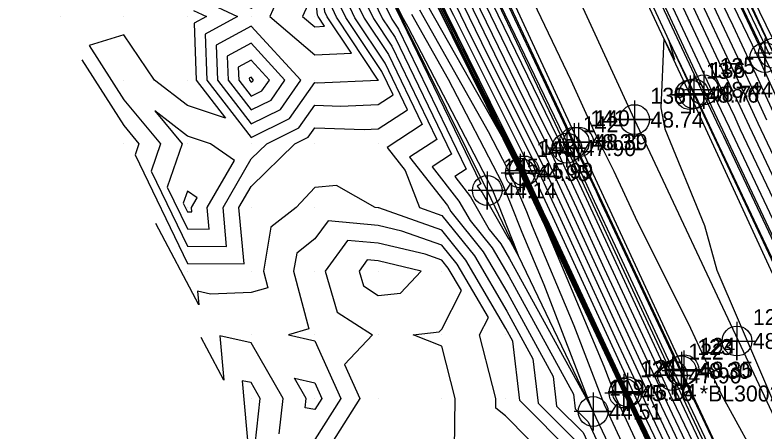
# Model space of a CAD drawing. Extents: x 2090860 to 2091277, y 159470 to 160080.
# Drawn here: x 2091052.9 to 2091170.8, y 159524.7 to 159590.2 of the extents above; entities that cross this region are included whole.
import ezdxf

# ---------------------------------------------------------------- set-up
doc = ezdxf.new("R2010")
doc.units = 0
for name, color, linetype in [('DTM Contours Major', 7, 'Continuous'), ('DTM Contours Minor', 7, 'Continuous'), ('Exist DTM Breakline', 7, 'Continuous'), ('Exist DTM Breakline Cogo Elevation', 7, 'Continuous'), ('Exist DTM Breakline Cogo Number', 7, 'Continuous'), ('Exist DTM Breakline Cogo Point CELL', 7, 'Continuous'), ('Exist DTM Crownline', 7, 'Continuous'), ('Exist DTM Crownline Cogo Elevation', 7, 'Continuous'), ('Exist DTM Crownline Cogo Number', 7, 'Continuous'), ('Exist DTM Crownline Cogo Point CELL', 7, 'Continuous'), ('Exist DTM QL2 LIDAR Elevation Point', 7, 'Continuous'), ('Exist Roads EOP', 7, 'Continuous'), ('Exist Roads EOP Cogo Elevation', 7, 'Continuous'), ('Exist Roads EOP Cogo Number', 7, 'Continuous'), ('Exist Roads EOP Cogo Point CELL', 7, 'Continuous'), ('Exist Roads EOT', 7, 'Continuous'), ('Exist Roads EOT Cogo Comment', 7, 'Continuous'), ('Exist Roads EOT Cogo Elevation', 7, 'Continuous'), ('Exist Roads EOT Cogo Number', 7, 'Continuous'), ('Exist Roads EOT Cogo Point CELL', 7, 'Continuous')]:
    doc.layers.add(name, color=color, linetype=linetype)

msp = doc.modelspace()

# ---------------------------------------------------------------- linework, layer by layer
at = {"layer": 'DTM Contours Major'}
for points in [[(2091110.01, 159579.99), (2091110, 159580), (2091103.43, 159589.88), (2091102.78, 159591.23), (2091101.95, 159599.1), (2091099.75, 159604.35), (2091092.87, 159614.02), (2091090, 159617.82), (2091083.3, 159616.7), (2091082.04, 159610), (2091081.38, 159608.62), (2091081.89, 159600), (2091082.49, 159592.49), (2091087.89, 159590), (2091082.79, 159587.21), (2091083.05, 159580), (2091090, 159570.96), (2091096.05, 159573.95), (2091100, 159579.61), (2091100.41, 159579.59), (2091110, 159579.99), (2091110.01, 159579.99)], [(2091171.96, 159584.5), (2091159.16, 159611.27)], [(2091172.41, 159574.21), (2091169.37, 159580.83), (2091168.62, 159582.42), (2091165.76, 159588.52), (2091155.65, 159609.47)], [(2091176.73, 159551.58), (2091166.95, 159572.18), (2091166.02, 159574.22), (2091163.43, 159579.67), (2091153.6, 159600.61)], [(2091123.21, 159594.52), (2091129.91, 159580.68), (2091136.47, 159567.62), (2091138.12, 159564.05), (2091140.2, 159559.58), (2091146.27, 159546.39), (2091152.79, 159532.35), (2091156.16, 159525.23), (2091159.5, 159518.23), (2091166.04, 159504.37), (2091172.36, 159491.13)], [(2091128.34, 159593.56), (2091139.93, 159569.54), (2091140.97, 159567.34), (2091143.92, 159560.98), (2091147.21, 159553.98), (2091156.59, 159533.79), (2091161.27, 159523.96), (2091163.21, 159519.86), (2091171.58, 159502.29)], [(2091107.49, 159593.3), (2091109.23, 159589.68), (2091112.12, 159585.33), (2091119.2, 159570.67), (2091114.92, 159567.89), (2091120.85, 159560.32), (2091121.4, 159559.35), (2091126.5, 159553), (2091130.34, 159546.45), (2091137.49, 159533.43), (2091138.02, 159528.79), (2091142.19, 159524.62), (2091146.07, 159516.26), (2091147.17, 159512.31), (2091150.06, 159501.29), (2091151.2, 159498.79), (2091159.61, 159487.39), (2091158.87, 159484.16)], [(2091119.62, 159592.62), (2091130.86, 159569.9), (2091132.95, 159565.75), (2091135.92, 159559.3), (2091136.42, 159558.22), (2091136.43, 159558.2), (2091136.46, 159558.15), (2091149.11, 159531.02), (2091149.46, 159530.28), (2091156.03, 159516.65), (2091157.29, 159514), (2091169.04, 159489.62), (2091168.66, 159489.37)], [(2091165.38, 159487.43), (2091166.95, 159488.49), (2091162.97, 159496.65), (2091154.19, 159515.65), (2091152.26, 159519.58), (2091147.4, 159530.11), (2091145.52, 159535.03), (2091136.24, 159557.07), (2091135.82, 159557.96), (2091132.52, 159565.03), (2091132.34, 159565.41), (2091129.86, 159570.34), (2091117.8, 159591.64)], [(2091090.23, 159579.77), (2091090.4, 159580), (2091090, 159580.43), (2091089.72, 159580.28), (2091089.73, 159580), (2091090, 159579.65), (2091090.23, 159579.77)], [(2091083.12, 159560), (2091087.39, 159567.39), (2091083.6, 159570), (2091080, 159571.2), (2091074.86, 159575.14), (2091079.15, 159570), (2091076.83, 159563.17), (2091080, 159556.61), (2091083.43, 159556.57), (2091083.12, 159560)], [(2091121.95, 159521.95), (2091122.09, 159530), (2091120, 159538.21), (2091115.49, 159540), (2091119.57, 159540.43), (2091120, 159540.89), (2091123.06, 159546.94), (2091121, 159550.46), (2091120, 159551.7), (2091117.36, 159552.64), (2091110, 159554.37), (2091105.18, 159554.82), (2091101.62, 159550), (2091103.54, 159543.54), (2091109.08, 159540), (2091104.66, 159535.34), (2091107.07, 159530), (2091102.04, 159522.04)], [(2091091.07, 159517.86), (2091090.65, 159519.35), (2091092.62, 159520), (2091090.36, 159520.36), (2091091.43, 159530), (2091090, 159532.48), (2091088.61, 159532.78), (2091089.65, 159521.06), (2091089.36, 159521.61)]]:
    msp.add_lwpolyline(points, dxfattribs=at)
at = {"layer": 'DTM Contours Minor'}
for points in [[(2091101.98, 159589.93), (2091101.61, 159590.71), (2091100.66, 159599.7), (2091099.92, 159601.47), (2091091.93, 159612.69), (2091090, 159615.24), (2091085.51, 159614.49), (2091084.66, 159610), (2091083.16, 159606.84), (2091083.56, 159600), (2091084.04, 159594.04), (2091090, 159591.29), (2091095.28, 159595.28), (2091092.94, 159590), (2091100, 159583.94), (2091105.79, 159584.21), (2091101.98, 159589.93)], [(2091173.78, 159574.72), (2091170.21, 159582.49), (2091169.92, 159583.11), (2091168.8, 159585.5), (2091156.91, 159610.13)], [(2091172.91, 159584.62), (2091161.2, 159608.69)], [(2091170.96, 159583.65), (2091159.14, 159608.41)], [(2091177.06, 159547.51), (2091165.59, 159571.67), (2091165.18, 159572.56), (2091162.13, 159578.99), (2091150.56, 159603.64)], [(2091131.42, 159598.52), (2091140.27, 159579.96), (2091144.16, 159571.35), (2091147, 159565.67), (2091150.37, 159558.45), (2091159.04, 159541.04), (2091163.85, 159530.74), (2091168.57, 159522.2), (2091174.47, 159509.57)], [(2091175.38, 159547.74), (2091164.28, 159571.14), (2091163.68, 159572.41), (2091160.86, 159578.35), (2091151.1, 159599.18)], [(2091127.83, 159563.02), (2091114.71, 159588.31), (2091113.97, 159589.62), (2091111.29, 159594.84), (2091111.22, 159594.96), (2091109.89, 159597.62), (2091111, 159594.95), (2091111.01, 159594.86), (2091113.57, 159589.53), (2091113.71, 159589.32), (2091126.1, 159563.68), (2091125.55, 159563.32), (2091126.31, 159562.35), (2091130.43, 159555.15), (2091130.63, 159554.91), (2091130.78, 159554.65), (2091132.15, 159552.14), (2091131.36, 159554.21), (2091130.99, 159555.1), (2091128.25, 159562.04), (2091127.83, 159563.02)], [(2091127.82, 159597.21), (2091138.56, 159574.44), (2091140.64, 159570.11), (2091144.22, 159562.5), (2091144.73, 159561.4), (2091156.04, 159537.32), (2091157.47, 159534.24), (2091158.19, 159532.74), (2091164.14, 159520.13), (2091165.09, 159518.14), (2091176.96, 159492.99)], [(2091176.41, 159555.65), (2091168.32, 159572.69), (2091166.86, 159575.87), (2091164.73, 159580.36), (2091156.64, 159597.59)], [(2091126.02, 159596), (2091138.04, 159571.18), (2091139.12, 159569.03), (2091139.39, 159568.44), (2091143.03, 159560.61), (2091144.03, 159558.44), (2091155.66, 159533.4), (2091156.21, 159532.23), (2091162.28, 159519.5), (2091163.24, 159517.46), (2091175.19, 159492.42)], [(2091171.53, 159583.93), (2091165.55, 159596.46)], [(2091124.14, 159595.01), (2091132.62, 159577.51), (2091137.36, 159568.09), (2091138.54, 159565.51), (2091141.14, 159559.92), (2091145.52, 159550.4), (2091153.75, 159532.7), (2091156.17, 159527.57), (2091160.42, 159518.66), (2091165.11, 159508.73), (2091173.3, 159491.56)], [(2091125.08, 159595.51), (2091135.33, 159574.35), (2091138.24, 159568.56), (2091138.97, 159566.98), (2091142.08, 159560.26), (2091144.77, 159554.42), (2091154.7, 159533.05), (2091156.19, 159529.9), (2091161.35, 159519.08), (2091164.18, 159513.1), (2091174.25, 159491.99)], [(2091176.08, 159559.72), (2091169.68, 159573.2), (2091167.7, 159577.53), (2091166.02, 159581.05), (2091159.68, 159594.57)], [(2091100.54, 159589.98), (2091100.43, 159590.19), (2091100, 159594.3), (2091098.09, 159590), (2091100, 159588.36), (2091101.56, 159588.44), (2091100.54, 159589.98)], [(2091108.66, 159593.82), (2091110.67, 159589.63), (2091112.65, 159586.66), (2091121.5, 159568.34), (2091118.46, 159566.36), (2091122.67, 159560.99), (2091124.41, 159557.95), (2091127.88, 159553.64), (2091130.49, 159549.18), (2091140.66, 159530.65), (2091140.93, 159528.36), (2091142.99, 159526.29), (2091148.27, 159514.9), (2091148.85, 159512.85), (2091150.34, 159507.13), (2091156.63, 159493.3), (2091161.33, 159486.92), (2091160.92, 159485.12)], [(2091109.84, 159594.34), (2091112.12, 159589.58), (2091113.18, 159587.99), (2091123.8, 159566.01), (2091122, 159564.84), (2091124.49, 159561.67), (2091127.42, 159556.55), (2091129.25, 159554.27), (2091130.63, 159551.92), (2091143.49, 159528.5), (2091136.08, 159547.82), (2091132.61, 159556.06), (2091130.79, 159560.67), (2091129.44, 159563.87)], [(2091121.34, 159593.53), (2091124.5, 159587.01), (2091134.71, 159566.68), (2091137.27, 159561.12), (2091138.31, 159558.89), (2091147.77, 159538.35), (2091150.88, 159531.66), (2091156.12, 159520.56), (2091157.64, 159517.38), (2091167.91, 159495.64), (2091170.47, 159490.27), (2091170.45, 159490.22)], [(2091122.27, 159594.02), (2091127.2, 159583.84), (2091135.59, 159567.15), (2091137.7, 159562.59), (2091139.25, 159559.23), (2091147.02, 159542.37), (2091151.83, 159532.01), (2091156.14, 159522.9), (2091158.57, 159517.81), (2091166.98, 159500), (2091171.42, 159490.7)], [(2091063.4, 159583.2), (2091070, 159572.84), (2091072.37, 159570), (2091071.77, 159568.23), (2091080, 159551.21), (2091088.89, 159551.11), (2091088.09, 159560), (2091090, 159563.3), (2091096.86, 159570), (2091098.96, 159571.04), (2091100, 159572.52), (2091107.76, 159572.24), (2091110, 159572.33), (2091114.6, 159575.33), (2091111.06, 159582.67), (2091106.33, 159589.78), (2091105.13, 159592.26)], [(2091106.31, 159592.78), (2091107.78, 159589.73), (2091111.59, 159584), (2091116.9, 159573), (2091111.38, 159569.41), (2091114.22, 159565.78), (2091116.48, 159560), (2091120, 159558.75), (2091125.12, 159552.37), (2091130.2, 159543.71), (2091134.31, 159536.22), (2091135.12, 159529.23), (2091141.39, 159522.94), (2091143.86, 159517.62), (2091145.5, 159511.77), (2091148.09, 159501.91), (2091148.63, 159500), (2091150, 159498.55), (2091157.89, 159487.86), (2091156.82, 159483.2)], [(2091119.2, 159592.39), (2091123.93, 159582.84), (2091132.63, 159565.57), (2091134.47, 159561.63), (2091136.12, 159558.08), (2091143.73, 159541.81), (2091148.81, 159530.9), (2091153.14, 159521.79), (2091155.67, 159516.52), (2091164.42, 159498.08), (2091168.58, 159489.45), (2091167.02, 159488.4)], [(2091119.41, 159592.5), (2091128.51, 159574.11), (2091132.78, 159565.65), (2091135.45, 159559.92), (2091136.28, 159558.14), (2091140.09, 159549.98), (2091148.96, 159530.96), (2091151.3, 159526.03), (2091155.85, 159516.59), (2091160.85, 159506.04), (2091168.81, 159489.54), (2091167.84, 159488.89)], [(2091120.4, 159593.03), (2091121.79, 159590.17), (2091133.83, 159566.21), (2091136.85, 159559.66), (2091137.37, 159558.55), (2091148.52, 159534.34), (2091149.92, 159531.31), (2091156.11, 159518.23), (2091156.71, 159516.96), (2091168.84, 159491.27), (2091169.53, 159489.84), (2091169.52, 159489.83)], [(2091112.31, 159577.66), (2091110.53, 159581.34), (2091104.88, 159589.83), (2091103.96, 159591.75)], [(2091164.56, 159486.95), (2091165.44, 159487.54), (2091157.04, 159504.73), (2091152.48, 159514.58), (2091147.96, 159523.81), (2091145.56, 159529.01), (2091140.8, 159541.42), (2091134.23, 159557.02), (2091133.33, 159559.3), (2091131.04, 159564.72), (2091127.32, 159571.89), (2091116.53, 159590.97)], [(2091166.2, 159487.92), (2091168.35, 159489.36), (2091167.98, 159490.11), (2091155.5, 159516.46), (2091154.97, 159517.54), (2091148.66, 159530.85), (2091147.36, 159533.64), (2091135.97, 159558.02), (2091133.49, 159563.33), (2091132.49, 159565.49), (2091119.34, 159591.57)], [(2091171.05, 159573.7), (2091168.54, 159579.18), (2091167.32, 159581.74), (2091162.72, 159591.55)], [(2091080.94, 159590.94), (2091082.99, 159590), (2091081.06, 159588.94), (2091081.38, 159580), (2091085.98, 159574.02), (2091080, 159576.01), (2091074.8, 159580), (2091070, 159587.09), (2091064.56, 159585.44), (2091070, 159576.9), (2091075.76, 159570), (2091074.3, 159565.7), (2091080, 159553.91), (2091086.16, 159553.84), (2091085.6, 159560), (2091090, 159567.61), (2091092.45, 159570), (2091097.51, 159572.49), (2091100, 159576.07), (2091104.08, 159575.92), (2091110, 159576.16), (2091112.31, 159577.66)], [(2091129.44, 159563.87), (2091121.02, 159580.1), (2091115.25, 159590.29)], [(2091094.6, 159575.4), (2091097.8, 159580), (2091090, 159588.47), (2091084.52, 159585.48), (2091084.72, 159580), (2091090, 159573.13), (2091094.6, 159575.4)], [(2091175.98, 159543.39), (2091164.06, 159568.64), (2091163.17, 159570.51), (2091159.88, 159577.48), (2091159.69, 159577.88), (2091159.03, 159579.28), (2091155.63, 159586.39), (2091156.55, 159583.25), (2091154.87, 159586.53), (2091154.4, 159575.64), (2091155.02, 159572.33), (2091161.24, 159557.18), (2091163.19, 159550.12), (2091173.59, 159526.02)], [(2091093.14, 159576.86), (2091095.33, 159580), (2091090, 159585.79), (2091086.26, 159583.74), (2091086.39, 159580), (2091090, 159575.31), (2091093.14, 159576.86)], [(2091091.69, 159578.31), (2091092.87, 159580), (2091090, 159583.11), (2091087.99, 159582.01), (2091088.06, 159580), (2091090, 159577.48), (2091091.69, 159578.31)], [(2091140.6, 159521.26), (2091132.22, 159529.67), (2091131.14, 159539), (2091130.05, 159540.98), (2091123.75, 159551.73), (2091120, 159556.4), (2091110.06, 159559.94), (2091110, 159559.95), (2091109.48, 159560), (2091103.44, 159563.44), (2091100, 159563.1), (2091097.06, 159560), (2091093.12, 159556.88), (2091091.93, 159550), (2091092.62, 159547.38), (2091090, 159546.63), (2091083.61, 159546.39), (2091081.58, 159546.84), (2091081.77, 159544.68), (2091075.01, 159557.47)], [(2091080.63, 159560), (2091081.5, 159561.5), (2091080, 159562.54), (2091079.35, 159560.65), (2091080, 159559.31), (2091080.7, 159559.3), (2091080.63, 159560)], [(2091137.15, 159520), (2091130, 159527.24), (2091128.46, 159528.46), (2091128.48, 159530), (2091127.97, 159532.03), (2091125.91, 159540), (2091127.29, 159542.71), (2091122.37, 159551.1), (2091120, 159554.05), (2091113.71, 159556.29), (2091110, 159557.16), (2091102.1, 159557.9), (2091100, 159555.06), (2091097.17, 159552.83), (2091096.69, 159550), (2091099.08, 159540.92), (2091095.88, 159540), (2091100, 159539.06), (2091104.09, 159530), (2091100, 159523.53)], [(2091110, 159551.58), (2091108.26, 159551.74), (2091106.97, 159550), (2091107.66, 159547.66), (2091110, 159546.17), (2091113.46, 159546.54), (2091116.73, 159550), (2091110, 159551.58)], [(2091094.43, 159524.43), (2091095.04, 159530), (2091090, 159538.73), (2091085.09, 159539.81), (2091085.71, 159532.87), (2091082.18, 159539.54)], [(2091096.82, 159533.18), (2091100, 159532.46), (2091101.11, 159530), (2091100, 159528.24), (2091098.49, 159528.49), (2091098.65, 159530), (2091096.82, 159533.18)]]:
    msp.add_lwpolyline(points, dxfattribs=at)
at = {"layer": 'Exist DTM Breakline'}
for points in [[(2091196.63, 159502.87), (2091177.33, 159544.14), (2091161.14, 159578.46), (2091145.39, 159612.39), (2091128.08, 159650.69), (2091112.84, 159682.38), (2091098.52, 159713.45), (2091088.42, 159738.26), (2091087.49, 159747.73)], [(2091206.49, 159507.9), (2091187.96, 159548.13), (2091170.75, 159583.55), (2091154.78, 159617.35), (2091136.61, 159654.77), (2091121.99, 159686.47), (2091108.44, 159717.46), (2091100.12, 159738.88)], [(2091168.33, 159489.35), (2091148.61, 159530.83), (2091132.31, 159565.39), (2091116.34, 159597.57), (2091098.7, 159637.59), (2091084.7, 159667.25), (2091067.16, 159699.24), (2091053.41, 159724.44), (2091052.89, 159730.3), (2091057.39, 159734.95)], [(2091169.18, 159489.68), (2091149.14, 159531.03), (2091132.91, 159565.73), (2091117.09, 159597.89), (2091099.25, 159637.73), (2091085.44, 159667.51), (2091069.3, 159700.06), (2091060.28, 159722.82), (2091058.46, 159734.2), (2091059.36, 159735), (2091060.62, 159735.81)], [(2091175.56, 159492.59), (2091156.22, 159533.6), (2091139.64, 159569.31), (2091124.33, 159601.66), (2091105.94, 159640.92), (2091091.73, 159670.47), (2091076.45, 159703.52), (2091059.36, 159735)], [(2091163.51, 159486.33), (2091143.76, 159527.93), (2091127.12, 159562.65), (2091111.11, 159594.9), (2091093.03, 159634.87), (2091078.89, 159664.39)], [(2091208.29, 159508.47), (2091189.15, 159548.51), (2091172.11, 159584.22), (2091156.47, 159618.15), (2091137.83, 159655.46)]]:
    msp.add_lwpolyline(points, dxfattribs=at)
at = {"layer": 'Exist DTM Breakline Cogo Point CELL'}
for points in [[(2091170.75, 159586.55), (2091170.75, 159580.55), (2091170.75, 159583.55), (2091173.75, 159583.55), (2091167.75, 159583.55)], [(2091172.11, 159587.22), (2091172.11, 159581.22), (2091172.11, 159584.22), (2091175.11, 159584.22), (2091169.11, 159584.22)], [(2091161.14, 159581.46), (2091161.14, 159575.46), (2091161.14, 159578.46), (2091164.14, 159578.46), (2091158.14, 159578.46)], [(2091139.64, 159572.31), (2091139.64, 159566.31), (2091139.64, 159569.31), (2091142.64, 159569.31), (2091136.64, 159569.31)], [(2091132.91, 159568.73), (2091132.91, 159562.73), (2091132.91, 159565.73), (2091135.91, 159565.73), (2091129.91, 159565.73)], [(2091132.31, 159568.39), (2091132.31, 159562.39), (2091132.31, 159565.39), (2091135.31, 159565.39), (2091129.31, 159565.39)], [(2091127.12, 159565.65), (2091127.12, 159559.65), (2091127.12, 159562.65), (2091130.12, 159562.65), (2091124.12, 159562.65)], [(2091156.22, 159536.6), (2091156.22, 159530.6), (2091156.22, 159533.6), (2091159.22, 159533.6), (2091153.22, 159533.6)], [(2091148.61, 159533.83), (2091148.61, 159527.83), (2091148.61, 159530.83), (2091151.61, 159530.83), (2091145.61, 159530.83)], [(2091149.14, 159534.03), (2091149.14, 159528.03), (2091149.14, 159531.03), (2091152.14, 159531.03), (2091146.14, 159531.03)], [(2091143.76, 159530.93), (2091143.76, 159524.93), (2091143.76, 159527.93), (2091146.76, 159527.93), (2091140.76, 159527.93)]]:
    msp.add_lwpolyline(points, dxfattribs=at)
for centre in [(2091172.11, 159584.22), (2091170.75, 159583.55), (2091161.14, 159578.46), (2091139.64, 159569.31), (2091132.31, 159565.39), (2091132.91, 159565.73), (2091127.12, 159562.65), (2091156.22, 159533.6), (2091149.14, 159531.03), (2091148.61, 159530.83), (2091143.76, 159527.93)]:
    msp.add_circle(centre, 2.34, dxfattribs=at)
at = {"layer": 'Exist DTM Crownline'}
msp.add_lwpolyline([(2091186.23, 159497.37), (2091150.27, 159573.79), (2091135.08, 159606.79), (2091117.27, 159645.44), (2091102.61, 159676.95), (2091088.1, 159708.38), (2091072.92, 159741.27)], dxfattribs=at)
at = {"layer": 'Exist DTM Crownline Cogo Point CELL'}
msp.add_lwpolyline([(2091150.27, 159576.79), (2091150.27, 159570.79), (2091150.27, 159573.79), (2091153.27, 159573.79), (2091147.27, 159573.79)], dxfattribs=at)
msp.add_circle((2091150.27, 159573.79), 2.34, dxfattribs=at)
at = {"layer": 'Exist DTM QL2 LIDAR Elevation Point'}
for p, q in [((2091060, 159590), (2091060, 159590)), ((2091070, 159590), (2091070, 159590)), ((2091080, 159590), (2091080, 159590)), ((2091090, 159590), (2091090, 159590)), ((2091100, 159590), (2091100, 159590)), ((2091070, 159580), (2091070, 159580)), ((2091080, 159580), (2091080, 159580)), ((2091090, 159580), (2091090, 159580)), ((2091100, 159580), (2091100, 159580)), ((2091110, 159580), (2091110, 159580)), ((2091070, 159570), (2091070, 159570)), ((2091080, 159570), (2091080, 159570)), ((2091090, 159570), (2091090, 159570)), ((2091100, 159570), (2091100, 159570)), ((2091110, 159570), (2091110, 159570)), ((2091080, 159560), (2091080, 159560)), ((2091090, 159560), (2091090, 159560)), ((2091100, 159560), (2091100, 159560)), ((2091110, 159560), (2091110, 159560)), ((2091120, 159560), (2091120, 159560)), ((2091080, 159550), (2091080, 159550)), ((2091090, 159550), (2091090, 159550)), ((2091100, 159550), (2091100, 159550)), ((2091110, 159550), (2091110, 159550)), ((2091120, 159550), (2091120, 159550)), ((2091090, 159540), (2091090, 159540)), ((2091100, 159540), (2091100, 159540)), ((2091110, 159540), (2091110, 159540)), ((2091120, 159540), (2091120, 159540)), ((2091130, 159540), (2091130, 159540)), ((2091090, 159530), (2091090, 159530)), ((2091100, 159530), (2091100, 159530)), ((2091110, 159530), (2091110, 159530)), ((2091120, 159530), (2091120, 159530)), ((2091130, 159530), (2091130, 159530))]:
    msp.add_line(p, q, dxfattribs=at)
at = {"layer": 'Exist Roads EOP'}
for points in [[(2091195.02, 159502.3), (2091175.82, 159543.3), (2091159.6, 159577.85), (2091143.94, 159611.54), (2091126.2, 159649.8), (2091111.24, 159681.73), (2091096.72, 159712.78), (2091082.12, 159745.37)], [(2091176.99, 159493), (2091157.63, 159534.32), (2091140.8, 159570.23), (2091125.68, 159602.45), (2091107.65, 159641.5), (2091093.37, 159671.64), (2091078.49, 159704.36), (2091063.61, 159736.87)]]:
    msp.add_lwpolyline(points, dxfattribs=at)
at = {"layer": 'Exist Roads EOP Cogo Point CELL'}
for points in [[(2091159.6, 159580.85), (2091159.6, 159574.85), (2091159.6, 159577.85), (2091162.6, 159577.85), (2091156.6, 159577.85)], [(2091140.8, 159573.23), (2091140.8, 159567.23), (2091140.8, 159570.23), (2091143.8, 159570.23), (2091137.8, 159570.23)], [(2091157.63, 159537.32), (2091157.63, 159531.32), (2091157.63, 159534.32), (2091160.63, 159534.32), (2091154.63, 159534.32)]]:
    msp.add_lwpolyline(points, dxfattribs=at)
for centre in [(2091159.6, 159577.85), (2091140.8, 159570.23), (2091157.63, 159534.32)]:
    msp.add_circle(centre, 2.34, dxfattribs=at)
at = {"layer": 'Exist Roads EOT'}
for points in [[(2091194.37, 159502.02), (2091175.12, 159542.8), (2091158.99, 159577.7), (2091143.37, 159611.22), (2091125.35, 159649.38), (2091110.43, 159681.3), (2091096.01, 159712.51), (2091081.14, 159744.98)], [(2091158.03, 159534.51), (2091141.45, 159570.27), (2091126.36, 159602.87), (2091108.39, 159641.68), (2091094.25, 159672.19), (2091079.27, 159704.67), (2091064.19, 159737.11)]]:
    msp.add_lwpolyline(points, dxfattribs=at)
at = {"layer": 'Exist Roads EOT Cogo Point CELL'}
for points in [[(2091158.99, 159580.7), (2091158.99, 159574.7), (2091158.99, 159577.7), (2091155.99, 159577.7), (2091161.99, 159577.7)], [(2091150.27, 159576.79), (2091150.27, 159570.79), (2091150.27, 159573.79), (2091147.27, 159573.79), (2091153.27, 159573.79)], [(2091141.45, 159573.27), (2091141.45, 159567.27), (2091141.45, 159570.27), (2091138.45, 159570.27), (2091144.45, 159570.27)], [(2091166.37, 159542.01), (2091166.37, 159536.01), (2091166.37, 159539.01), (2091163.37, 159539.01), (2091169.37, 159539.01)], [(2091158.03, 159537.51), (2091158.03, 159531.51), (2091158.03, 159534.51), (2091155.03, 159534.51), (2091161.03, 159534.51)]]:
    msp.add_lwpolyline(points, dxfattribs=at)
for centre in [(2091158.99, 159577.7), (2091150.27, 159573.79), (2091141.45, 159570.27), (2091166.37, 159539.01), (2091158.03, 159534.51)]:
    msp.add_circle(centre, 2.34, dxfattribs=at)

# ---------------------------------------------------------------- texts
at = {"layer": 'Exist DTM Breakline Cogo Elevation'}
for s, p in [('48.44', (2091163.64, 159577.21)), ('47.90', (2091142.14, 159568.06)), ('44.95', (2091134.81, 159564.14)), ('45.99', (2091135.41, 159564.48)), ('44.14', (2091129.62, 159561.4)), ('47.90', (2091158.72, 159532.35)), ('45.16', (2091151.11, 159529.58)), ('46.04', (2091151.64, 159529.78)), ('44.51', (2091146.26, 159526.68))]:
    msp.add_text(s, height=2.5, dxfattribs=at).set_placement(p)
at = {"layer": 'Exist DTM Breakline Cogo Number'}
for s, p in [('135', (2091163.64, 159580.96)), ('142', (2091142.14, 159571.81)), ('144', (2091134.81, 159567.89)), ('143', (2091135.41, 159568.23)), ('145', (2091129.62, 159565.15)), ('122', (2091158.72, 159536.1)), ('120', (2091151.11, 159533.33)), ('121', (2091151.64, 159533.53)), ('119', (2091146.26, 159530.43))]:
    msp.add_text(s, height=2.5, dxfattribs=at).set_placement(p)
at = {"layer": 'Exist DTM Crownline Cogo Elevation'}
msp.add_text('48.74', height=2.5, dxfattribs=at).set_placement((2091152.77, 159572.54))
at = {"layer": 'Exist DTM Crownline Cogo Number'}
msp.add_text('138', height=2.5, dxfattribs=at).set_placement((2091152.77, 159576.29))
at = {"layer": 'Exist Roads EOP Cogo Elevation'}
for s, p in [('48.77', (2091162.1, 159576.6)), ('48.31', (2091143.3, 159568.98)), ('48.30', (2091160.13, 159533.07))]:
    msp.add_text(s, height=2.5, dxfattribs=at).set_placement(p)
at = {"layer": 'Exist Roads EOP Cogo Number'}
for s, p in [('136', (2091162.1, 159580.35)), ('141', (2091143.3, 159572.73)), ('123', (2091160.13, 159536.82))]:
    msp.add_text(s, height=2.5, dxfattribs=at).set_placement(p)
at = {"layer": 'Exist Roads EOT Cogo Comment'}
msp.add_text('*BL30022', height=2.5, dxfattribs=at).set_placement((2091160.53, 159529.51))
at = {"layer": 'Exist Roads EOT Cogo Elevation'}
for s, p in [('48.76', (2091161.49, 159576.45)), ('48.74', (2091152.77, 159572.54)), ('48.39', (2091143.95, 159569.02)), ('48.71', (2091168.87, 159537.76)), ('48.35', (2091160.53, 159533.26))]:
    msp.add_text(s, height=2.5, dxfattribs=at).set_placement(p)
at = {"layer": 'Exist Roads EOT Cogo Number'}
for s, p in [('137', (2091161.49, 159580.2)), ('139', (2091152.77, 159576.29)), ('140', (2091143.95, 159572.77)), ('125', (2091168.87, 159541.51)), ('124', (2091160.53, 159537.01))]:
    msp.add_text(s, height=2.5, dxfattribs=at).set_placement(p)

doc.saveas('drawing.dxf')
